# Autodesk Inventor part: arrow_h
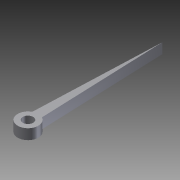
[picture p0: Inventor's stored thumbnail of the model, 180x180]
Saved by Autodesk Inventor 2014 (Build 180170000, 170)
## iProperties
Created: 2013-08
Part Number: arrow_h
Material: Типовые
Document SubType Name: Modeling
Designer: ed
Density: 1 g/cm^3
Appearance: По умолчанию
Author: ed
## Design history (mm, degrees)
sketch "Эскиз1"
  geometry: L1 (-4.663, 8.846)-(0, 130); L2 (0, 130)-(4.663, 8.846); L3 (0, 0)-(0, 53.426); C1 r 5 at (0, 0); A1 r 10 centre (0, 0) between (-4.663, 8.846) and (4.663, 8.846); 1 further point
  constraints: 6 end point, 2 centre point, 2 coincident, 2 point on circle, 1 tangent, 1 vertical, 1 other
  dimensions: "d0" = 20 diameter of A1; "d1" = 10 diameter of C1; "d2" = 130 distance of L1.end point (0, 0)
extrude "Выдавливание1" new body sketch "Эскиз1" distance "d3" = 10; taper "d4" = 0 deg
node "Твердое тело1"
